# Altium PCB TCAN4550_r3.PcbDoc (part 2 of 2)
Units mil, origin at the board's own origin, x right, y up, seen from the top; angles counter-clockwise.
Board outline 2000 x 1400 mil, 2 copper layers (Top Layer, Bottom Layer), stack 62 mil thick; 75 components, 46 nets, 194 pads, 17 vias.
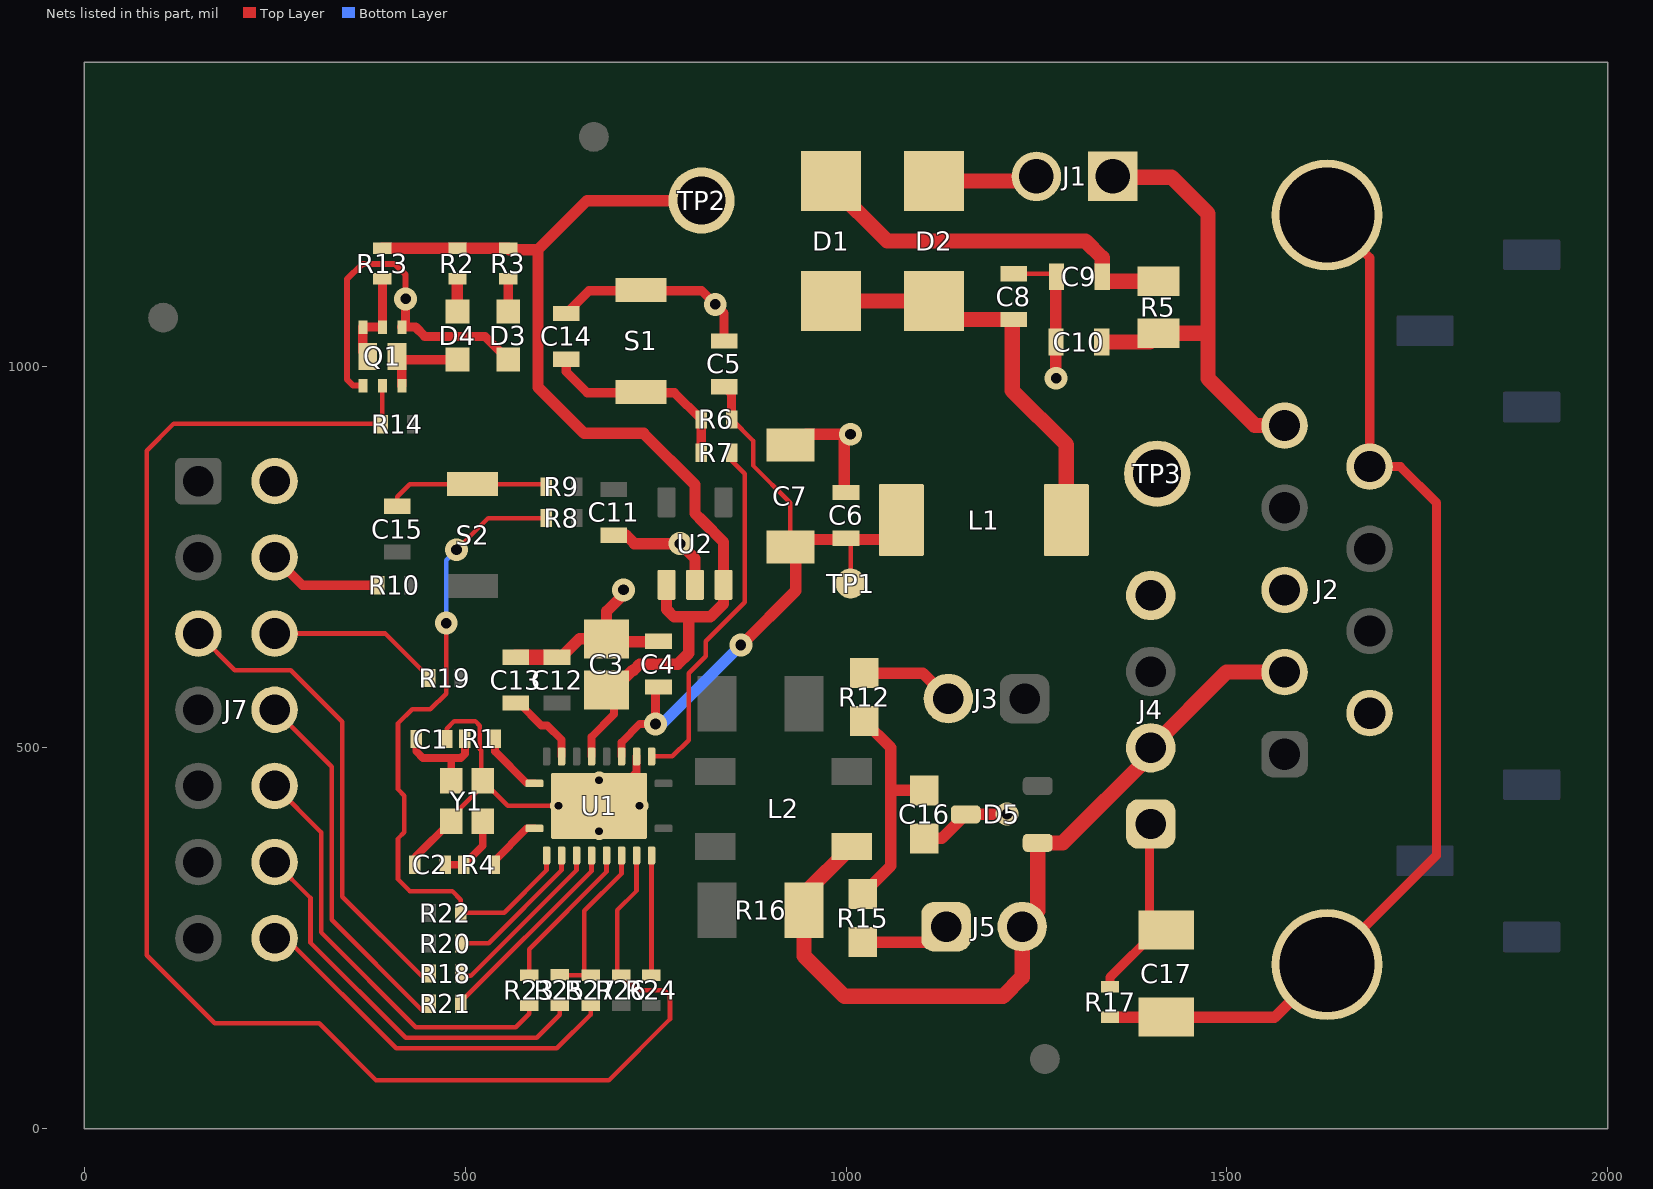
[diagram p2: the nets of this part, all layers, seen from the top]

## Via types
v1: diameter 30, hole 14, Top Layer to Bottom Layer, 13 vias
v2: diameter 23, hole 10, Top Layer to Bottom Layer, 4 vias

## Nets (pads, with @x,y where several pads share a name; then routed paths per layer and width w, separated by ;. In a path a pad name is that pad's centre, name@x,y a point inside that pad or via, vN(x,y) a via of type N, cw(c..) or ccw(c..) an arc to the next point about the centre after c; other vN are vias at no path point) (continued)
CANL_BUS: D5.1 J2.2 J4.2 J5.2 L2.3 R16.2 | length 1095.1
  Top Layer w20: L2.3@1007.53,370.62 945.05,308.13 R16.2@945.05,286.88 945.05,226.73 998,173.78 1206.04,173.78 1231.27,199.01 J5.2@1231.27,265.3 1251.66,285.69 D5.1@1251.66,375.2 1284.37,375.2 1400,490.82 J4.2@1400,500 1499.39,599.39 J2.2@1575.54,599.39
CRYSTAL1: C1.1 R1.2 Y1.1 | length 136.7
  Top Layer w10: C1.1@435.89,511.49 435.89,495.46 444.74,486.61 480,486.61 481.66,484.95 ; Y1.1@481.66,456.58 481.66,484.95 ; R1.2@499.38,511.86 500,511.24 500,492.28 494.34,486.61 481.66,486.61 481.66,484.95
CRYSTAL3: C2.1 R4.2 Y1.3 | length 91.2
  Top Layer w10: C2.1@474.24,346.43 R4.2@498.14,346.43 523,371.29 Y1.3@523,403.43
DB9_VBAT: C10.1 J1.1 J2.5 R5.2 | length 632.6
  Top Layer w20: C10.1@1335.54,1032.57 1398.61,1032.57 R5.2@1410.15,1044.11 1475,1044.11 ; J1.1@1367,1267 1367,1249 1427.08,1249 1475,1201.08 1475,1044.11 ; J2.5@1575.54,923.01 1536.59,923.01 1475,984.6 1475,1044.11
FLTR: C13.1 U1.18 | length 102.3
  Top Layer w10: C13.1@566.37,558.9 570.49,558.9 600.1,529.3 608.13,529.3 626.63,510.8 U1.18@626.63,488.73
GND: C1.2 C2.2 C3.2 C4.2 C5.2 C6.2 C7.2 C8.2 C9.2 C10.2 C11.2 C12.2 C13.2 C14.2 C16.1 C17.2 D2.2 D3.1 D5.3 J1.2 J2.3 J2.6 J4.1 J4.4 J7.2 J7.4 Q1.1 Q1.4 R10.1 R17.1 S1.1 TP3.1 U1.13 U1.21 U2.2 Y1.2 Y1.4 | length 2786.6
  Top Layer w6: C1.2@475.89,511.49 475.89,525.05 485.95,535.11 513.16,535.11 519.38,528.89 519.38,498.08 521,496.45 521,458.58 Y1.4@523,456.58 ; Y1.2@481.66,403.43 481.66,408.97 523,450.31 Y1.4@523,456.58 ; C12.2@620.73,618.9 626.16,618.9 C12.2@626.63,619.37 ; U1.21@675.85,423.77 v2(622.7,423.77) 555.82,423.77 Y1.4@523,456.58 ; C8.2@1220,1122.16 1270.71,1122.16 1275.54,1117.33 C9.2@1276.31,1118.1
  Top Layer w8: Q1.1@365.81,975.48 353.2,975.48 345,983.68 345,1115 364.85,1134.85 408.36,1134.85 422.05,1121.16 v1(422.05,1089.24) ; Q1.4@416.99,1052.26 Q1.4@422.05,1057.32
  Top Layer w10: C2.2@434.24,346.43 434.24,350.95 434.95,351.66 434.95,356.73 Y1.2@481.66,403.43 ; U1.21@675.85,423.77 680.5,423.77 725.06,468.32 U1.13@725.06,488.73
  Top Layer w12: J7.4@250,750 286.58,713.42 R10.1@387.05,713.42 ; Q1.4@416.99,1052.26 434.91,1052.26 447.16,1040 526.07,1040 D3.1@556.7,1009.37 ; Q1.4@422.05,1057.32 v1(422.05,1089.24) ; C14.2@623.78,1069.86 632.64,1069.86 C14.2@632.78,1070 662.72,1099.94 810.46,1099.94 v1(828.4,1082) 840,1070.4 C5.2@840,1034 ; R17.1@1346.5,186.15 1346.5,198.73 1408.36,260.59 C17.2@1420.58,260.59 1398.15,283.03 J4.1@1398.15,413.19
  Top Layer w15: C12.2@626.63,619.37 650.26,643 C3.2@685.69,643 687.05,644.36 C3.2@695.5,644.36 ; C11.2@695.33,779 711.33,779 722.33,768 v1(782.14,768) 801.82,748.31 U2.2@801.82,713.87 ; v1@707.93,701.21 685.69,678.97 685.69,654.18 C3.2@695.5,644.36 ; C4.2@754.28,639.27 700.6,639.27 C3.2@695.5,644.36 ; C7.2@927,897.36 933.54,897.36 947.69,911.51 v1(1006,911.51) 997.48,902.99 C6.2@997.48,833.42 ; C16.1@1102.8,381.25 1125.82,381.25 D5.3@1157.17,412.6 1204.42,412.6 1205.01,413.19 v1(1211.31,413.19) ; D2.2@1115.6,1243.81 D2.2@1135.6,1223.8 ; C9.2@1275.54,1117.33 C10.2@1275.54,1032.57 1275.54,985.32 v1(1275.86,985)
  Top Layer w20: C13.2@566.37,618.9 C12.2@620.73,618.9 ; D2.2@1115.6,1243.81 1243.81,1243.81 J1.2@1250,1250
  other v1: 707.93,707.29
  other v2: 675.85,390.3 729,423.77 675.85,457.23
GPIO1: R20.1 U1.3 | length 191.5
  Top Layer w6: R20.1@494.34,243.7 531.14,243.7 626.63,339.19 U1.3@626.63,358.81
GPIO_RST: J7.6 R19.1 | length 227.8
  Top Layer w6: J7.6@250,650 395.13,650 R19.1@453.57,591.55
GPO2: R24.1 U1.9 | length 157.1
  Top Layer w6: R24.1@744.74,201.74 U1.9@744.74,358.81
nCS: R25.2 R27.2 U1.7 | length 218.1
  Top Layer w6: R25.2@615.76,201.74 656.61,201.74 656.61,285.97 705.37,334.73 U1.7@705.37,358.81
nINT: Q1.2 R14.1 R26.1 U1.8 | length 2104.5
  Top Layer w6: Q1.2@391.4,975.48 391.4,925.42 117.42,925.42 82,890 82,227.88 171.54,138.35 308.65,138.35 383.1,63.9 688.86,63.9 769,144.03 769,174.22 761.47,181.74 726.2,181.74 706.29,201.65 R26.1@700,201.65 ; R26.1@697.95,201.65 R26.1@700,201.65 ; U1.8@725.06,358.81 725.06,312.11 700,287.05 R26.1@700,201.65
NINT_LED_INV: Q1.5 Q1.6 Q1.7 R13.1 | length 129.9
  Top Layer w12: Q1.7@372.19,1013.87 365.81,1020.25 Q1.6@365.81,1052.26 Q1.5@391.4,1052.26 Q1.5@391.4,1052.26 R13.1@391.44,1115.47
NINT_LEDA: D4.2 R2.1 | length 43.2
  Top Layer w15: R2.1@490,1115.47 490,1072.46 D4.2@490.1,1072.36
NINT_LEDC: D4.1 Q1.3 Q1.8 | length 116
  Top Layer w12: Q1.8@410.61,1013.87 Q1.8@415.12,1009.37 ; Q1.3@416.99,975.48 416.99,1007.49 Q1.8@415.12,1009.37 ; D4.1@490.1,1009.37 Q1.8@415.12,1009.37
nWRKQ: R8.1 R22.1 U1.2 | length 886.6
  Top Layer w6: v1(475.24,663.61) 475.24,608.09 475.2,608.06 475.2,571.2 454.55,550.55 430.55,550.55 412,532 412,445.48 420.44,437.04 420.44,389.35 412,380.91 412,327.46 427.46,312 483,312 494.34,300.66 R22.1@494.34,283.71 ; v1(488.83,760) 530.4,801.58 R8.1@606.63,801.58 ; R22.1@494.34,283.14 R22.1@494.34,283.71 ; U1.2@606.95,358.81 606.95,339.13 551.54,283.71 R22.1@494.34,283.71
  Bottom Layer w6: v1(475.24,663.61) 475.24,746.41 v1(488.83,760)
OSC1: R4.1 U1.1 | length 75.6
  Top Layer w10: R4.1@538.14,346.43 538.14,351.19 581.19,394.24 U1.1@591.2,394.24
OSC2: R1.1 U1.20 | length 85.9
  Top Layer w10: R1.1@539.38,511.86 539.38,495.16 581.24,453.29 U1.20@591.2,453.29
RST_SW: C15.2 R9.1 S2.1 | length 216.1
  Top Layer w6: C15.2@411.13,817.12 411.13,829.5 427.56,845.93 S2.1@510,845.93 603.18,845.93 R9.1@606.63,842.48
SCLK: R18.1 U1.4 | length 229
  Top Layer w6: R18.1@494.34,200.57 507.64,200.57 646.32,339.26 U1.4@646.32,358.81
SDI: R21.2 U1.5 | length 274
  Top Layer w6: R21.2@493.67,156.14 493.67,165.82 666,338.15 U1.5@666,358.81
SDO: R23.2 U1.6 | length 199.1
  Top Layer w6: R23.2@584.26,201.74 584.26,235.77 685.69,337.2 U1.6@685.69,358.81
SHIELD_GND: C17.1 J2.9 J2.10 J2.11 R17.2 | length 1410.5
  Top Layer w12: J2.10@1631.45,1199.19 1687.35,1143.29 J2.9@1687.35,869.07 1727.65,869.07 1775,821.72 1775,358.89 J2.11@1676.93,260.82
  Top Layer w15: R17.2@1346.5,146.15 1420.31,146.15 C17.1@1420.58,146.42 ; C17.1@1450.24,146.15 1562.26,146.15 J2.11@1631.45,215.33 J2.11@1676.93,260.82
SPI_CLK: J7.5 R18.2 | length 623.3
  Top Layer w6: J7.5@150,650 197.96,602.04 271.16,602.04 339,534.2 339,304.63 443.05,200.57 R18.2@452.69,200.57
SPI_CS_0: J7.12 R25.1 | length 529.1
  Top Layer w6: J7.12@250,350 297.13,302.87 297.13,244.32 422.05,119.39 594.3,119.39 624.46,149.56 R25.1@624.46,161.91
SPI_CS_1: J7.14 R27.1 | length 505.1
  Top Layer w6: J7.14@250,250 265.03,250 409.51,105.52 620.6,105.52 665,149.92 R27.1@665,161.74
SPI_MISO: J7.10 R23.1 | length 560.4
  Top Layer w6: J7.10@250,450 311,389 311,257.76 435.49,133.27 566.49,133.27 584.26,151.03 R23.1@584.26,161.74
SPI_MOSI: J7.8 R21.1 | length 485
  Top Layer w6: J7.8@250,550 325,475 325,274.31 442.09,157.22 R21.1@454.75,157.22
SPLIT_TERM: C16.2 R12.1 R15.2 | length 301.1
  Top Layer w15: R15.2@1021.72,307.85 1058.86,344.99 1058.86,444.24 ; R12.1@1023.79,535.11 1058.9,500 1058.86,499.96 1058.86,444.24 ; C16.2@1102.8,444.24 1058.86,444.24
TERMH: J3.2 R12.2 | length 124.4
  Top Layer w15: R12.2@1023.79,598.1 1100.76,598.1 J3.2@1134.31,564.55
TERML: J5.1 R15.1 | length 118
  Top Layer w15: R15.1@1021.72,244.86 1110.83,244.86 J5.1@1131.27,265.3
VBAT: C8.1 D1.1 D2.1 L1.2 | length 543.1
  Top Layer w20: D1.1@980.32,1086.33 D2.1@1115.6,1086.33 1125.44,1086.33 1149.6,1062.16 C8.1@1220,1062.16 1218.07,1060.24 1218.07,968.97 1289.17,897.87 L1.2@1289.17,799
VBAT_EXT_R: C9.1 D1.2 R5.1 | length 501.9
  Top Layer w20: D1.2@980.32,1243.81 980.32,1238.86 1054.11,1165.07 1314.45,1165.07 1336.31,1143.21 C9.1@1336.31,1118.1 1342.2,1112.22 R5.1@1410.15,1112.22
VCCOUT: C3.1 R2.2 R3.2 R13.2 TP2.1 U1.16 U2.1 U2.3 | length 1427
  Top Layer w10: U1.16@666,488.73 666,514.38 695.5,543.88 C3.1@695.5,561.72 ; C3.1@695.5,576.45 C3.1@695.5,577.43
  Top Layer w15: R13.2@391.44,1155.47 R2.2@490,1155.47 R3.2@556.7,1155.47 558.2,1153.97 595.74,1153.97 ; C3.1@695.5,577.43 720.11,602.04 721.58,602.04 729.09,609.54 778.99,609.54 793.47,624.02 793.47,671.8 ; U2.1@764.42,713.87 764.42,681.8 774.42,671.8 793.47,671.8 ; TP2.1@810.46,1218.28 660.05,1218.28 595.74,1153.97 ; 595.74,1153.97 595.74,973.36 656.45,912.66 734.34,912.66 801.81,845.19 801.81,807.69 812.04,797.46 812.04,797.26 839.22,770.07 U2.3@839.22,713.87 839.22,689.16 821.86,671.8 793.47,671.8
VCCOUT_LEDA: D3.2 R3.1 | length 43.1
  Top Layer w12: D3.2@556.7,1072.36 R3.1@556.7,1115.47
VSUP: C4.1 C5.1 C6.1 C7.1 L1.1 R6.2 TP1.1 U1.14 | length 886.1
  Top Layer w6: R6.2@849.89,931 878,902.89 878,870.5 927,821.5 C7.1@927,763.5 ; C6.1@1000,775 1001.58,773.42 1006,769 TP1.1@1006,715.63
  Top Layer w10: U1.14@705.37,488.73 705.37,507.3 729.37,531.29 v1(750,531.29)
  Top Layer w12: v1(750,531.29) 750,575.95 C4.1@753.32,579.27 ; C5.1@840,974 849.89,964.11 R6.2@849.89,931
  Top Layer w15: v1(862.07,635) 862.93,635 934,706.07 934,756.5 C7.1@927,763.5 ; C7.1@944.7,773.42 1001.58,773.42 1047.06,773.42 L1.1@1072.64,799
  Bottom Layer w15: v1(750,531.29) 758.36,531.29 v1(862.07,635)
WAKE: R7.2 U1.12 | length 461.9
  Top Layer w6: U1.12@744.74,488.73 772.09,488.73 793.47,510.11 793.47,598.03 815.8,620.36 815.8,639.75 867,690.95 867,859.88 R7.2@850,876.88
WAKE_SW: C14.1 R6.1 R7.1 S1.2 | length 272.2
  Top Layer w12: C14.1@623.78,1009.86 632.78,1009.86 632.78,993.68 660.38,966.08 774.81,966.08 R6.1@809.89,931 810,930.89 R7.1@810,887.08
pads on no net: FID1.1 FID2.1 FID3.1 J2.1 J2.4 J2.8 J6.1 J6.2 J6.3 J7.1 J7.3 J8.1 J8.2 J8.3 U1.15 U2.4

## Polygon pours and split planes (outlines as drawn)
GND on Bottom Layer "BOTTOM_LAYER_GND_P000" (solid, remove dead copper, pour order 0): 1950,1300 1900,1350 100,1350 50,1300 50,100 100,50 1900,50 1950,100

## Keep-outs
Keep-Out Layer:
  text ".Layer_Name" at 577,-858.49 h60

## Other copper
Top Layer:
  text ".Layer_Name" at 577,-858.49 h60
Bottom Layer:
  text ".Layer_Name" at 577,-858.49 h60

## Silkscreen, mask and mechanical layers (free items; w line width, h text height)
Top Overlay:
  text "TCAN4550" at 255.33,1292.79 h80
  text "'.PRJ_Number'.PCB_Rev" at 261.1,1223.14 h70
  text ".Layer_Name" at 577,-858.49 h60
Bottom Overlay:
  text ".Layer_Name" at 577,-858.49 h60
Top Paste:
  text ".Layer_Name" at 577,-858.49 h60
Bottom Paste:
  text ".Layer_Name" at 577,-858.49 h60
Top Solder:
  text ".Layer_Name" at 577,-858.49 h60
  text ".Layer_Name" at 577,-858.49 h60
Bottom Solder:
  text ".Layer_Name" at 577,-858.49 h60
Drill Guide:
  text ".Layer_Name" at 577,-858.49 h60
M1 Board Outline:
  the board outline again, w10
  text ".Layer_Name" at 577,-858.49 h60
M2 Board Dimensions:
  rectangle: 0,-275 125,-150
  rectangle: 125,-400 500,-275
  lines w7: 0,-275 1000,-275 ; 125,-400 125,-150 ; 250,-400 250,-150 ; 500,-400 500,-150 ; 750,-400 750,-150 ; 0,-400 1000,-400 1000,-150 0,-150 0,-400
  text ".Layer_Name" at 577,-858.49 h60
M3 3D STEP Top:
  text ".Layer_Name" at 577,-858.49 h60
M4 3D STEP Bottom:
  text ".Layer_Name" at 577,-858.49 h60
M5 Assembly Top:
  lines w10: -292,-930.17 6308,-930.17 ; -292,-726.83 6310,-726.83 ; -292,-523.5 -292,-1133.5 3713,-1133.5 6310,-1133.5 6310,-523.5 -291.5,-523.5 -291.5,-1133.5 1284,-1133.5 ; 2173,-1133.5 2173,-523.5 ; 3440,-726.83 3440,-523.5 ; 4280,-726.83 4280,-523.5 ; 4902,-1140 4902,-937.17
  text "COMPONENTS MARKED 'DNP' SHOULD NOT BE POPULATED." at 1153.5,-318.5 h60
  text "ASSEMBLY VARIANT:" at 1153,-434 h60
  text ".VariantName" at 2189,-434 h60
  text "PCB VIEWED FROM TOP SIDE" at -228.5,-655.67 h60
  text "BOARD #:" at 2248,-655.67 h60
  text ".PRJ_Number" at 2793.5,-655.67 h60
  text "REV:" at 3638,-655.67 h60
  text ".PCB_Rev" at 3929.5,-655.67 h60
  text "SVN REV:" at 4476,-655.67 h60
  text ".VersionControl_RevNumber" at 4982,-655.67 h60
  text "TID #:" at 2248,-859 h60
  text ".TID" at 2793.5,-859 h60
  text "PLOT NAME =" at -228.5,-1064.34 h60
  text ".plot_File_Name" at 577,-1064.34 h60
  text "GENERATED    :" at 2250,-1064.34 h60
  text ".Print_Date" at 3119.5,-1064.34 h60
  text ".Print_Time" at 3848.5,-1064.34 h60
  text "TEXAS INSTRUMENTS" at 5113,-1064.34 h60
M6 Assembly Bottom:
  lines w10: -292.5,-727.33 6309.5,-727.33 ; -290.5,-930.67 6309.5,-930.67 ; 1115.5,-1140.5 1115.5,-937.67 ; 1737.5,-727.33 1737.5,-524 ; 2577.5,-727.33 2577.5,-524 ; 3844.5,-1134 3844.5,-524 ; 4733.5,-1134 6309,-1134 6309,-524 -292.5,-524 -292.5,-1134 2304.5,-1134 6309.5,-1134 6309.5,-524
  text "COMPONENTS MARKED 'DNP' SHOULD NOT BE POPULATED." at 6102,-318 h60
  text ".VariantName" at 5058,-434 h60
  text "ASSEMBLY VARIANT:" at 6097,-434 h60
  text ".VersionControl_RevNumber" at 1035.5,-656.17 h60
  text "SVN REV:" at 1541.5,-656.17 h60
  text ".PCB_Rev" at 2088,-656.17 h60
  text "REV:" at 2379.5,-656.17 h60
  text ".PRJ_Number" at 3224,-656.17 h60
  text "BOARD #:" at 3769.5,-656.17 h60
  text "PCB VIEWED FROM BOTTOM SIDE" at 6246,-656.17 h60
  text ".TID" at 3224,-859.5 h60
  text "TID #:" at 3769.5,-859.5 h60
  text "TEXAS INSTRUMENTS" at 904.5,-1064.84 h60
  text ".Print_Time" at 2169,-1064.84 h60
  text ".Print_Date" at 2898,-1064.84 h60
  text "GENERATED    :" at 3767.5,-1064.84 h60
  text ".plot_File_Name" at 5440.5,-1064.84 h60
  text "PLOT NAME =" at 6246,-1064.84 h60
M9 Title Sheet:
  drawing of 57 lines, arcs and shapes, not listed
  text "1" at 739.84,8036.5 h70
  text "2" at 3235.5,8036.5 h70
  text "3" at 5724.84,8036.5 h70
  text "4" at 8231.51,8036.5 h70
  text "5" at 10730.5,8036.5 h70
  text "6" at 13235.5,8036.5 h70
  text "A" at -416.5,6893.5 h70
  text "A" at 14383.5,6893.5 h70
  text "B" at -416.5,4513.5 h70
  text "B" at 14383.5,4513.5 h70
  text "C" at -416.5,2138.5 h70
  text "C" at 14383.5,2138.5 h70
  text "PROJECT TITLE:" at 11343.5,277.5 h45
  text ".PRJ_Title" at 11393.5,144.17 h70
  text "DESIGNED FOR:" at 11343.5,-23.5 h45
  text ".PRJ_Customer" at 11393.5,-163.5 h70
  text "D" at -416.5,-231.5 h70
  text "D" at 14383.5,-231.5 h70
  text "FILE NAME:" at 11343.5,-323.5 h45
  text ".PCB_File_Name_No_Path" at 11393.5,-443.5 h70
  text "Texas Instruments (TI) and/or its licensors do not warrant the accuracy or completeness of this specification" at 6374,-605.34 h45
  text "ENGINEER:" at 11343.5,-613.5 h45
  text "LAYOUT BY:" at 12848.5,-613.5 h45
  text "or any information contained therein. TI and/or its licensors do not warrant that this design will meet" at 6329.01,-718 h45
  text ".PRJ_Engineer" at 11393.5,-768.49 h70
  text ".PCB_Layout" at 12899,-768.49 h70
  text "the specifications, will be suitable for your application or fit for any particular purpose, or will operate in" at 6329.01,-830.67 h45
  text ".Layer_Name" at 577,-858.49 h60
  text "ALTIUM DESIGNER VERSION:" at 12848.5,-923.5 h45
  text "an implementation. TI and/or its licensors do not warrant that the design is production worthy. You should" at 6329.01,-943.33 h45
  text "completely validate and test your design implementation to confirm the system functionality for your application." at 6374,-1056 h45
  text ".print_Scale" at 11393.5,-1056.83 h70
  text ".Application_BuildNumber" at 12899,-1056.83 h70
  text "1" at 739.84,-1263.5 h70
  text "2" at 3235.5,-1263.5 h70
  text "3" at 5724.84,-1263.5 h70
  text "4" at 8231.51,-1263.5 h70
  text "5" at 10730.5,-1263.5 h70
  text "6" at 13235.5,-1263.5 h70
M10 Fab Notes:
  drawing of 189 lines, arcs and shapes, not listed
  text "DESIGN INFORMATION" at 12382.02,6356.17 h60
  text "MIN. TRACK WIDTH:" at 11737.46,6224.05 h60
  text "8" at 12833.7,6224.05 h60
  text "MIL" at 12988.46,6224.05 h60
  text "MIN. CLEARANCE:" at 11737.46,6099.92 h60
  text "0.2" at 12773.7,6099.93 h60
  text "mm" at 12988.46,6099.92 h60
  text "MIN. VIA PAD SIZE:" at 11737.46,5975.8 h60
  text "24" at 12803.71,5975.8 h60
  text "MIL" at 12988.46,5975.8 h60
  text "0.05mm (2MIL)" at 12432.46,5845.9 h60
  text "MINIMUM ANNULAR RING" at 11408.23,5837.67 h60
  text "EXTERNAL" at 13140.46,5837.67 h60
  text "PER" at 11608.23,5727.55 h60
  text "IPC-D-275 CLASS 2 LEVEL C" at 11828.23,5727.54 h60
  text "MIL, HOLES" at 13316.46,5627.07 h60
  text "+/-" at 12924,5618.48 h60
  text "+/-" at 13778,5618.48 h60
  text "REGISTRATION TOLERANCES:" at 11408.23,5617.42 h60
  text "METAL" at 12608,5617.42 h60
  text "5" at 13184.2,5617.42 h60
  text "3" at 14017.2,5617.42 h60
  text "MIL" at 14133.46,5617.42 h60
  text "HOLE SIZE TOLERANCE (UNLESS OTHERWISE SPECIFIED):" at 11408.23,5519.1 h60
  text "+/-" at 13778,5516.23 h60
  text "3" at 14017.2,5515.17 h60
  text "MIL" at 14133.46,5515.17 h60
  text "MATERIAL:" at 11333.46,5377.52 h60
  text "FR-4 High Tg" at 12319.9,5249 h60
  text "X" at 12175.46,5241.01 h60
  text "FR-408" at 11754.46,5236.49 h60
  text "OTHER" at 13242.46,5236.49 h60
  text "62 MIL (1.6mm) +/-10%" at 12074.56,5093.46 h60
  text "X" at 11954.46,5091.01 h60
  text "THICKNESS:" at 11408.23,5085.24 h60
  text "OTHER" at 13359.46,5085.24 h60
  text "TOLERANCE:" at 11408.23,4946.92 h60
  text "X" at 12256.46,4946.92 h60
  text "ANSI IPC-6012 TYPE 3 CLASS 2" at 12434.48,4946.92 h60
  text "OTHER +/-" at 12434.46,4802.73 h60
  text "BOW & TWIST:" at 11408.23,4657.54 h60
  text "X" at 12256.46,4657.54 h60
  text "ANSI IPC-6012 TYPE 3 CLASS 2" at 12434.48,4657.54 h60
  text "OTHER +/-" at 12434.46,4510.85 h60
  text "DRILLING:" at 11333.46,4380.23 h60
  text "NC_DRILL FILES" at 13094.46,4275.04 h60
  text "REFERENCE:" at 11408.23,4271.1 h60
  text "X" at 12065.46,4271.01 h60
  text "AS SHOWN" at 12243.46,4271.1 h60
  text "X" at 12966.46,4271.1 h60
  text "OTHER" at 13392.46,4128.85 h60
  text "PTH COPPER THICKNESS:" at 11407.91,4125.32 h60
  text "X" at 12547.14,4125.32 h60
  text "20-30 um" at 12675.14,4125.32 h60
  text "BOARD FINISH:" at 11333.46,3977.73 h60
  text "SILKSCREEN:" at 11488.68,3867.6 h60
  text "X" at 12446.46,3867.6 h60
  text "TOP" at 12563.46,3867.6 h60
  text "X" at 12956.46,3867.6 h60
  text "BOTTOM" at 13074.46,3867.6 h60
  text "SILKSCREEN COLOR:" at 11488.68,3712.41 h60
  text "X" at 12445.46,3712.41 h60
  text "WHITE" at 12563.46,3712.41 h60
  text "OTHER" at 13074.46,3712.41 h60
  text "X" at 12576.46,3568.96 h60
  text "GREEN" at 12694.46,3568.96 h60
  text "OTHER" at 13312.46,3568.96 h60
  text "SOLDER RESIST COLOR:" at 11488.68,3562.1 h60
  text "X" at 12576.46,3414.71 h60
  text "MATTE" at 12694.46,3414.71 h60
  text "SEMI-GLOSS" at 13312,3414.07 h60
  text "IMMERSION GOLD (ENIG)" at 12394.46,3241.94 h60
  text "ENEPIG" at 13732,3234.72 h60
  text "SURFACE FINISH:" at 11333.46,3233.72 h60
  text "X" at 11510,3100 h60
  text "IMM. TIN/SILVER OR EQUIV" at 11663,3096.4 h60
  text "OTHER" at 13094.46,3092.47 h60
  text "ARRAY/PANEL:" at 11333.46,2937.09 h60
  text "CUT AND TRIM PER M1 BOARD OUTLINE" at 12394.46,2928.87 h60
  text "N.C. ROUTE" at 12394.46,2792.9 h60
  text "X" at 13082.46,2792.9 h60
  text "V. SCORE" at 13260.46,2792.9 h60
  text "CERTIFICATION:" at 11333.46,2663.77 h60
  text "MATERIALS AND WORKMANSHIP FOR ALL PCBS" at 12058.46,2663.77 h60
  text "TO MEET OR EXCEED THE REQUIREMENTS OF:" at 12058.46,2569.71 h60
  text "X" at 11695.97,2441.08 h60
  text "ANSI IPC-A-600F CLASS ->" at 11823.96,2441.08 h60
  text "X" at 13471.97,2441.08 h60
  text "2" at 13581.96,2441.08 h60
  text "1" at 13266.96,2439.58 h60
  text "3" at 13935.96,2439.58 h60
  text "X" at 12507.97,2293.39 h60
  text "RoHS" at 12635.96,2293.39 h60
  text "OTHER" at 13280.36,2293.39 h60
  text "PER ORDER" at 13677.42,2293.39 h60
  text "ALL BOARDS MUST MEET OR EXCEED UL94-V0 REQUIREMENTS." at 11361,2139.57 h60
  text "PCB MUST BEAR THE UL94V-0 UL REGISTERED MATERIAL ID NUMBER" at 11361,2023.5 h60
  text "ADDITIONAL REQUIREMENTS:" at 11333.46,1854.08 h60
  text "MICROSECTION:" at 11408.23,1746.95 h60
  text "YES" at 12313.96,1746.95 h60
  text "REQUIRED" at 13175.46,1602.62 h60
  text "BARE BOARD ELEC. TEST:" at 11408.23,1599.76 h60
  text "X" at 12592.5,1599.76 h60
  text "NONE" at 12713.96,1599.76 h60
  text "PER ORDER" at 13767.46,1599.76 h60
  text "XX MIL VIAS REQUIRE NON-CONDUCTIVE FILL AND PLANARIZE" at 11576.38,1394.82 h59
  text "XX MIL VIAS REQUIRE CONDUCTIVE FILL AND PLANARIZE" at 11584.38,1290.84 h60
  text "OUTER XX MIL TRACES REQUIRE 50 OHM SINGLE-ENDED IMPEDANCE" at 11583.39,1127.46 h58
  text "LAYER 2 & 3 (INNER LAYERS) XX MIL WIDE, XX MIL SPACE / TRACES REQUIRE 100 OHM DIFFERENTIAL IMPEDANCE" at 11575.39,891.74 h60
  text ".Layer_Name" at 577,-858.49 h60
M11 Gerber Information:
  lines w10: -292,-930.17 6308,-930.17 ; -292,-726.83 6310,-726.83 ; -292,-523.5 -292,-1133.5 3713,-1133.5 6310,-1133.5 6310,-523.5 -291.5,-523.5 -291.5,-1133.5 1284,-1133.5 ; 2173,-1133.5 2173,-523.5 ; 3440,-726.83 3440,-523.5 ; 4280,-726.83 4280,-523.5 ; 4902,-1140 4902,-937.17
  text "ALL ARTWORK VIEWED FROM TOP SIDE" at -228.5,-655.67 h60
  text "BOARD #:" at 2248,-655.67 h60
  text ".PRJ_Number" at 2793.5,-655.67 h60
  text "REV:" at 3638,-655.67 h60
  text ".PCB_Rev" at 3929.5,-655.67 h60
  text "SVN REV:" at 4476,-655.67 h60
  text ".VersionControl_RevNumber" at 4982,-655.67 h60
  text "LAYER NAME =" at -228.5,-858.49 h60
  text "TID #:" at 2248,-859 h60
  text ".TID" at 2793.5,-859 h60
  text "PLOT NAME =" at -228.5,-1064.34 h60
  text ".plot_File_Name" at 577,-1064.34 h60
  text "GENERATED    :" at 2250,-1064.34 h60
  text ".Print_Date" at 3119.5,-1064.34 h60
  text ".Print_Time" at 3848.5,-1064.34 h60
  text "TEXAS INSTRUMENTS" at 5113,-1064.34 h60
M12 Stackup:
  drawing of 191 lines, arcs and shapes, not listed
  text "Layer" at 9811.59,7627.44 h60
  text "Name" at 10221.51,7627.44 h60
  text "Material" at 11151.25,7627.44 h60
  text "Thickness" at 12011.02,7627.44 h60
  text "Constant" at 12660.85,7627.44 h60
  text "Board Layer Stack" at 13230.71,7627.44 h60
  text "1" at 9811.59,7507.44 h60
  text "Top Overlay" at 10221.51,7507.44 h60
  text "2" at 9811.59,7387.44 h60
  text "Top Solder" at 10221.51,7387.44 h60
  text "Solder Resist" at 11151.25,7387.44 h60
  text "0.40mil" at 12011.02,7387.44 h60
  text "3.5" at 12660.85,7387.44 h60
  text "3" at 9811.59,7267.44 h60
  text "Top Layer" at 10221.51,7267.44 h60
  text "Copper" at 11151.25,7267.44 h60
  text "1.40mil" at 12011.02,7267.44 h60
  text "4" at 9811.59,7147.44 h60
  text "Dielectric1" at 10221.51,7147.44 h60
  text "FR-4" at 11151.25,7147.44 h60
  text "59.20mil" at 12011.02,7147.44 h60
  text "4.8" at 12660.85,7147.44 h60
  text "5" at 9811.59,7027.44 h60
  text "Bottom Layer" at 10221.51,7027.44 h60
  text "Copper" at 11151.25,7027.44 h60
  text "1.40mil" at 12011.02,7027.44 h60
  text "6" at 9811.59,6907.44 h60
  text "Bottom Solder" at 10221.51,6907.44 h60
  text "Solder Resist" at 11151.25,6907.44 h60
  text "0.40mil" at 12011.02,6907.44 h60
  text "3.5" at 12660.85,6907.44 h60
  text "7" at 9811.59,6787.44 h60
  text "Bottom Overlay" at 10221.51,6787.44 h60
  text ".Layer_Name" at 577,-858.49 h60
M13 Component Bodies Top:
  text ".Layer_Name" at 577,-858.49 h60
M14 Component Bodies Bottom:
  text ".Layer_Name" at 577,-858.49 h60
M15 Courtyards Top:
  text ".Layer_Name" at 577,-858.49 h60
M16 Courtyards Bottom:
  text ".Layer_Name" at 577,-858.49 h60
Drill Drawing:
  circle w10: c2564,802.95 r27.63
  lines w10: 2536.37,278.04 2564,291.85 2591.62,278.04 2577.81,305.67 2591.62,333.29 2564,319.48 2536.37,333.29 2550.18,305.67 2536.37,278.04 ; 2536.37,457.61 2591.62,457.61 2564,402.36 2536.37,457.61 ; 2536.37,526.68 2591.62,526.68 2591.62,581.93 2536.37,581.93 2536.37,526.68 ; 2536.37,664.81 2550.18,664.81 2564,651 2577.81,664.81 2591.62,664.81 2577.81,678.63 2591.62,692.44 2577.81,692.44 2564,706.25 2550.18,692.44 2536.37,692.44 2550.18,678.63 2536.37,664.81 ; 2536.37,913.45 2550.18,913.45 2550.18,899.64 2577.81,899.64 2577.81,913.45 2591.62,913.45 2591.62,941.08 2577.81,941.08 2577.81,954.89 2550.18,954.89 2550.18,941.08 2536.37,941.08 2536.37,913.45 ; 2536.37,1023.96 2591.62,1023.96 2591.62,1079.21 2536.37,1079.21 2536.37,1023.96 ; 2536.37,1148.28 2536.37,1162.09 2550.18,1175.91 2536.37,1189.72 2536.37,1203.53 2550.18,1203.53 2564,1189.72 2577.81,1203.53 2591.62,1203.53 2591.62,1189.72 2577.81,1175.91 2591.62,1162.09 2591.62,1148.28 2577.81,1148.28 2564,1162.09 2550.18,1148.28 2536.37,1148.28 ; 2547.42,537.73 2580.57,537.73 2580.57,570.88 2547.42,570.88 2547.42,537.73
  lines w12: 2486.28,240.74 5717.77,240.74 ; 2486.28,1235.3 5717.77,1235.3 ; 2824.14,116.42 2824.14,1359.62 ; 3156.14,116.42 3156.14,1359.62 ; 3792.7,116.42 3792.7,1359.62 ; 4051.84,116.42 4051.84,1359.62 ; 4427,116.42 4427,1359.62 ; 5151.33,116.42 5151.33,1359.62 ; 2486.28,116.42 5717.77,116.42 5717.77,1359.62 2486.28,1359.62 2486.28,116.42
  text "Symbol" at 2560.87,1272.6 h72
  text "Quantity" at 2861.44,1272.6 h72
  text "Finished Hole Size" at 3193.44,1272.6 h72
  text "Plated" at 3830,1272.6 h72
  text "Hole Type" at 4089.14,1272.6 h72
  text "Drill Layer Pair" at 4464.3,1272.6 h72
  text "Hole Tolerance" at 5188.63,1272.6 h72
  text "4" at 2861.44,1148.28 h60
  text "10.00mil (0.254mm)" at 3193.44,1148.28 h60
  text "PTH" at 3830,1148.28 h60
  text "Round" at 4089.14,1148.28 h60
  text "Top Layer - Bottom Layer" at 4464.3,1148.28 h60
  text "13" at 2861.44,1023.96 h60
  text "14.00mil (0.356mm)" at 3193.44,1023.96 h60
  text "PTH" at 3830,1023.96 h60
  text "Round" at 4089.14,1023.96 h60
  text "Top Layer - Bottom Layer" at 4464.3,1023.96 h60
  text "8" at 2861.44,899.64 h60
  text "40.00mil (1.016mm)" at 3193.44,899.64 h60
  text "PTH" at 3830,899.64 h60
  text "Round" at 4089.14,899.64 h60
  text "Top Layer - Bottom Layer" at 4464.3,899.64 h60
  text "14" at 2861.44,775.32 h60
  text "40.16mil (1.020mm)" at 3193.44,775.32 h60
  text "PTH" at 3830,775.32 h60
  text "Round" at 4089.14,775.32 h60
  text "Top Layer - Bottom Layer" at 4464.3,775.32 h60
  text "9" at 2861.44,651 h60
  text "40.95mil (1.040mm)" at 3193.44,651 h60
  text "PTH" at 3830,651 h60
  text "Round" at 4089.14,651 h60
  text "Top Layer - Bottom Layer" at 4464.3,651 h60
  text "2" at 2861.44,526.68 h60
  text "45.28mil (1.150mm)" at 3193.44,526.68 h60
  text "PTH" at 3830,526.68 h60
  text "Round" at 4089.14,526.68 h60
  text "Top Layer - Bottom Layer" at 4464.3,526.68 h60
  text "2" at 2861.44,402.36 h60
  text "63.00mil (1.600mm)" at 3193.44,402.36 h60
  text "PTH" at 3830,402.36 h60
  text "Round" at 4089.14,402.36 h60
  text "Top Layer - Bottom Layer" at 4464.3,402.36 h60
  text "2" at 2861.44,278.04 h60
  text "124.80mil (3.170mm)" at 3193.44,278.04 h60
  text "PTH" at 3830,278.04 h60
  text "Round" at 4089.14,278.04 h60
  text "Top Layer - Bottom Layer" at 4464.3,278.04 h60
  text "54 Total" at 2861.44,153.72 h60
  text ".Layer_Name" at 577,-858.49 h60
M17 Embedded Cavity:
  text ".Layer_Name" at 577,-858.49 h60
M18 Embedded Assembly:
  text ".Layer_Name" at 577,-858.49 h60
M19 Embedded Keepout:
  text ".Layer_Name" at 577,-858.49 h60

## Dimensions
0,-400 to 1000,-400 on M2 Board Dimensions
0,1400 to 2000,0 on M2 Board Dimensions
2000,0 to 0,1400 on M2 Board Dimensions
